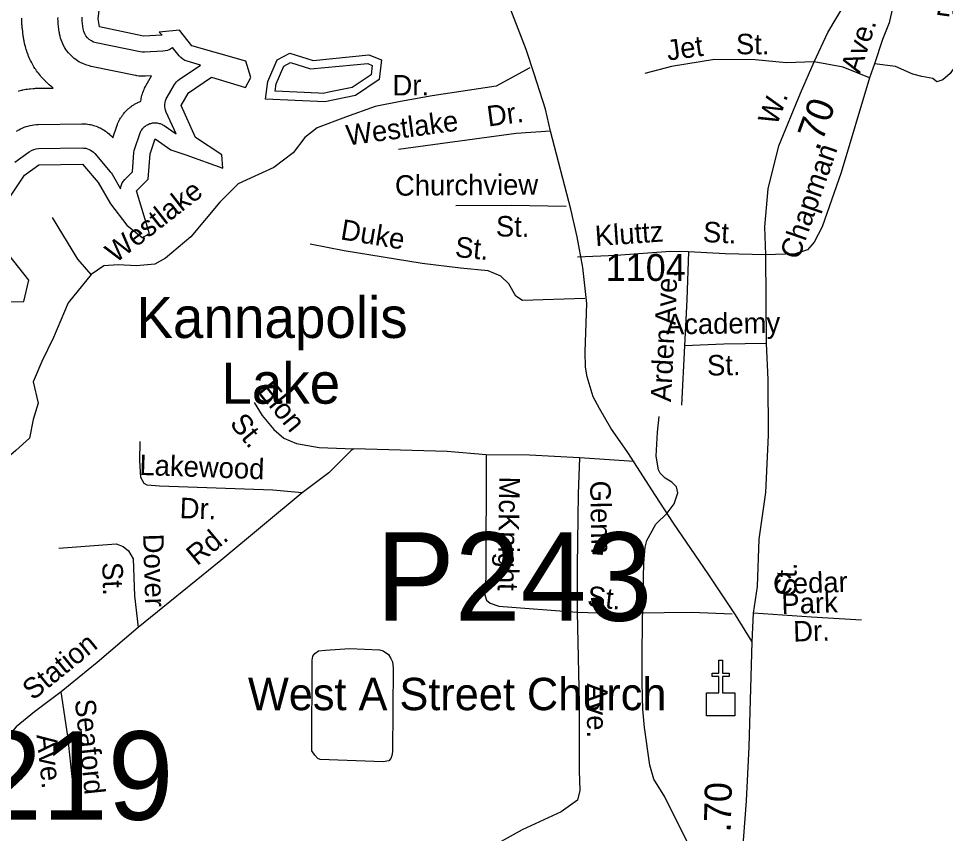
# Model space of a CAD drawing. Extents: x 1473865 to 1648260, y 639067 to 773536.
# Drawn here: x 1510919 to 1515215, y 645258 to 649038 of the extents above; entities that cross this region are included whole.
import ezdxf

# ---------------------------------------------------------------- set-up
doc = ezdxf.new("R2010")
doc.units = 0
for name, color, linetype in [('Exist Cultural Church CELL', 7, 'Continuous'), ('Exist Cultural Church Label', 7, 'Continuous'), ('Exist Hydrographic Buffer Line', 7, 'Continuous'), ('Exist Hydrographic Creek Single Shore', 7, 'Continuous'), ('Exist Hydrographic Lake Shore', 7, 'Continuous'), ('Exist Hydrographic Lake Shore Label', 7, 'Continuous'), ('Exist Hydrographic Misc Water Feature', 7, 'Continuous'), ('Exist Road Non-System Type 51', 7, 'Continuous'), ('Exist Road Non-System Type 51 Label', 7, 'Continuous'), ('Exist Road Secondary Mileage Hundredths English Label', 7, 'Continuous'), ('Exist Road Secondary Structure Pipe Number Label', 7, 'Continuous'), ('Exist Road Secondary Structure Standard Bridge Number Label', 7, 'Continuous'), ('Exist Road Secondary Type 51 Attributed', 7, 'Continuous'), ('Exist Road Secondary Type 51 Label', 7, 'Continuous'), ('Exist Road Secondary Type 51 Number Label', 7, 'Continuous')]:
    doc.layers.add(name, color=color, linetype=linetype)

msp = doc.modelspace()

# ---------------------------------------------------------------- linework, layer by layer
at = {"layer": 'Exist Cultural Church CELL'}
msp.add_lwpolyline([(1514108, 645909.7), (1514164.9, 645909.8), (1514164.9, 645986), (1514132.9, 645986), (1514132.9, 646001.9), (1514164.9, 646001.9), (1514164.9, 646062.1), (1514180.9, 646062.1), (1514180.9, 646001.9), (1514212.9, 646001.9), (1514212.9, 645986), (1514180.9, 645986), (1514180.9, 645909.8), (1514238.6, 645909.7), (1514238.6, 645803.3), (1514108, 645803.3)], close=True, dxfattribs=at)
at = {"layer": 'Exist Hydrographic Buffer Line'}
for points in [[(1510902.1, 648371.9), (1510968.4, 648420.2), (1510978.2, 648426.2), (1510988.8, 648430.7), (1511000, 648433.4), (1511011.4, 648434.5), (1511213.5, 648437.5), (1511221.8, 648437.2), (1511229.9, 648436), (1511237.8, 648433.9), (1511245.5, 648430.9), (1511252.8, 648427.1), (1511259.6, 648422.5), (1511265.9, 648417.3), (1511271.6, 648411.3), (1511344, 648326.9), (1511348.3, 648321.4), (1511352, 648315.5), (1511390.5, 648248.7), (1511392, 648256.9), (1511395.1, 648266.5), (1511399.5, 648275.7), (1511405.1, 648284.1), (1511411.8, 648291.8), (1511446.7, 648326.6), (1511453.6, 648416.5), (1511454.9, 648425.8), (1511457.3, 648434.8), (1511480.4, 648503.1), (1511481.9, 648507.2), (1511483.6, 648511.1), (1511485.6, 648515), (1511487.7, 648518.7), (1511490.1, 648522.3), (1511492.7, 648525.8), (1511495.5, 648529.1), (1511498.5, 648532.2), (1511501.6, 648535.2), (1511504.9, 648538), (1511508.4, 648540.5), (1511512, 648542.9), (1511515.8, 648545.1), (1511519.6, 648547), (1511523.6, 648548.8), (1511527.6, 648550.2), (1511531.8, 648551.5), (1511536, 648552.5), (1511540.2, 648553.3), (1511544.5, 648553.8), (1511548.8, 648554.1), (1511553.2, 648554.1), (1511557.5, 648553.9), (1511561.8, 648553.4), (1511566, 648552.7), (1511570.3, 648551.7), (1511574.4, 648550.5), (1511578.5, 648549.1), (1511582.5, 648547.4), (1511586.4, 648545.5), (1511590.1, 648543.4), (1511593.8, 648541), (1511648.9, 648503.3), (1511603.4, 648604.1), (1511600.2, 648612.5), (1511598, 648621.1), (1511596.9, 648630), (1511596.8, 648638.9), (1511597.8, 648647.7), (1511599.9, 648656.4), (1511602.9, 648664.8), (1511606.9, 648672.8), (1511641, 648731.2), (1511645.6, 648738.1), (1511650.9, 648744.5), (1511656.9, 648750.3), (1511663.6, 648755.4), (1511761.5, 648822.1), (1511700.9, 648839.4), (1511689.9, 648843.4), (1511679.7, 648849.1), (1511670.6, 648856.4), (1511662.6, 648864.9), (1511632.2, 648903.3), (1511628.4, 648900.1), (1511619.2, 648894.4), (1511609.3, 648890.1), (1511598.8, 648887.3), (1511588.1, 648886), (1511501.8, 648881.8), (1511492.4, 648882), (1511483.1, 648883.3), (1511278, 648925.5), (1511266.8, 648928.7), (1511256.2, 648933.7), (1511246.5, 648940.2), (1511238, 648948.1), (1511230.8, 648957.2), (1511225.1, 648967.4), (1511221, 648978.3), (1511218.7, 648989.7), (1511214, 649027), (1511213.4, 649035.9), (1511213.9, 649044.8)], [(1510909.7, 648515.5), (1510919.5, 648521.6), (1510927, 648525.8), (1510934.8, 648529.4), (1510945.4, 648533.9), (1510953.4, 648536.9), (1510961.7, 648539.3), (1510972.8, 648542.1), (1510981.2, 648543.9), (1510989.7, 648545), (1511001.2, 648546), (1511005.5, 648546.3), (1511009.8, 648546.5), (1511211.9, 648549.5), (1511214.9, 648549.5), (1511218, 648549.4), (1511226.2, 648549.1), (1511232.3, 648548.7), (1511238.4, 648547.9), (1511246.6, 648546.7), (1511252.6, 648545.6), (1511258.6, 648544.2), (1511266.5, 648542.1), (1511272.4, 648540.4), (1511278.2, 648538.3), (1511285.9, 648535.4), (1511291.5, 648533), (1511297.1, 648530.3), (1511304.3, 648526.5), (1511309.7, 648523.6), (1511314.9, 648520.3), (1511321.8, 648515.7), (1511326.8, 648512.2), (1511331.6, 648508.4), (1511337.9, 648503.1), (1511342.5, 648499), (1511346.8, 648494.7), (1511352.5, 648488.8), (1511354.6, 648486.5), (1511356, 648484.9), (1511374.3, 648538.9), (1511374.8, 648540.5), (1511375.3, 648542), (1511376.8, 648546), (1511378, 648549), (1511379.2, 648552), (1511381, 648556), (1511382.3, 648558.9), (1511383.7, 648561.8), (1511385.7, 648565.7), (1511387.2, 648568.5), (1511388.8, 648571.3), (1511390.9, 648575.1), (1511392.6, 648577.8), (1511394.4, 648580.6), (1511396.7, 648584.2), (1511398.6, 648586.8), (1511400.5, 648589.4), (1511403.1, 648592.9), (1511405, 648595.5), (1511407.1, 648598), (1511409.9, 648601.3), (1511412, 648603.7), (1511414.2, 648606.1), (1511417.1, 648609.2), (1511419.4, 648611.5), (1511421.7, 648613.8), (1511424.9, 648616.7), (1511427.2, 648618.9), (1511429.7, 648621), (1511433, 648623.8), (1511435.5, 648625.8), (1511438.1, 648627.8), (1511441.5, 648630.4), (1511444.1, 648632.3), (1511446.8, 648634.1), (1511450.4, 648636.5), (1511453.2, 648638.2), (1511455.9, 648639.9), (1511459.7, 648642), (1511462.5, 648643.6), (1511465.3, 648645.1), (1511469.2, 648647), (1511472.1, 648648.5), (1511475.1, 648649.8), (1511479, 648651.5), (1511482, 648652.7), (1511485, 648653.9), (1511485.9, 648654.2), (1511486.5, 648660.2), (1511487.5, 648666.8), (1511488.8, 648673.3), (1511490.8, 648682), (1511492.5, 648688.4), (1511494.6, 648694.8), (1511497.7, 648703.1), (1511500.2, 648709.3), (1511503, 648715.4), (1511507, 648723.3), (1511508.6, 648726.3), (1511510.2, 648729.2), (1511534.7, 648771.3), (1511507.2, 648770), (1511503.7, 648769.8), (1511500.1, 648769.8), (1511490.7, 648770), (1511483.7, 648770.3), (1511476.7, 648771.1), (1511467.4, 648772.4), (1511463.9, 648772.9), (1511460.5, 648773.6), (1511255.4, 648815.8), (1511251.1, 648816.8), (1511246.9, 648817.9), (1511235.7, 648821.1), (1511227.5, 648823.9), (1511219.4, 648827.2), (1511208.9, 648832.2), (1511201.1, 648836.1), (1511193.7, 648840.7), (1511184.1, 648847.2), (1511177, 648852.3), (1511170.4, 648858), (1511161.9, 648865.9), (1511155.7, 648872.1), (1511150.1, 648878.7), (1511142.9, 648887.8), (1511137.7, 648894.9), (1511133.2, 648902.3), (1511127.5, 648912.4), (1511123.5, 648920.2), (1511120.1, 648928.2), (1511116.1, 648939.1), (1511113.3, 648947.4), (1511111.3, 648955.8), (1511108.9, 648967.3), (1511108.1, 648971.5), (1511107.5, 648975.8), (1511102.9, 649013.1), (1511102.5, 649016.4), (1511102.2, 649019.8), (1511101.7, 649028.6), (1511101.4, 649035.3), (1511101.6, 649041.9)], [(1510917.8, 648701.5), (1510920.9, 648702.3), (1510932, 648705.1), (1510935.2, 648705.8), (1510938.3, 648706.5), (1510946.7, 648708.3), (1510953.1, 648709.5), (1510959.4, 648710.4), (1510968, 648711.6), (1510971.2, 648711.9), (1510974.4, 648712.3), (1510985.8, 648713.3), (1510987.4, 648713.5), (1510989, 648713.6), (1510993.3, 648713.9), (1510996.5, 648714.1), (1510999.7, 648714.2), (1511004, 648714.4), (1511005.7, 648714.4), (1511007.3, 648714.5), (1511079.5, 648715.5), (1511078, 648716.6), (1511072.8, 648720.6), (1511067.7, 648724.7), (1511061.1, 648730.4), (1511058.7, 648732.6), (1511056.3, 648734.8), (1511047.7, 648742.7), (1511045.3, 648744.9), (1511043, 648747.2), (1511036.9, 648753.4), (1511032.3, 648758.1), (1511028, 648762.9), (1511022.3, 648769.6), (1511020.3, 648772.1), (1511018.2, 648774.6), (1511011, 648783.8), (1511009, 648786.3), (1511007, 648789), (1511001.9, 648796), (1510998.2, 648801.3), (1510994.7, 648806.8), (1510990.1, 648814.3), (1510988.4, 648817.1), (1510986.8, 648819.9), (1510981.1, 648830), (1510979.5, 648832.9), (1510978, 648835.8), (1510974, 648843.5), (1510971.1, 648849.4), (1510968.5, 648855.4), (1510965.1, 648863.4), (1510963.9, 648866.4), (1510962.7, 648869.5), (1510958.7, 648880.4), (1510957.6, 648883.5), (1510956.5, 648886.5), (1510953.8, 648894.8), (1510951.9, 648901.1), (1510950.2, 648907.4), (1510948.1, 648915.8), (1510947.4, 648919), (1510946.7, 648922.2), (1510944.3, 648933.6), (1510944, 648935.2), (1510943.7, 648936.8), (1510942.9, 648941.1), (1510942.4, 648944.3), (1510941.9, 648947.5), (1510941.2, 648951.8), (1510941, 648953.4), (1510940.8, 648955.1), (1510936.2, 648992.4), (1510936, 648993.6), (1510935.9, 648994.8), (1510935.5, 648998.1), (1510935.3, 649000.6), (1510935, 649003.1), (1510934.8, 649006.4), (1510934.7, 649007.7), (1510934.6, 649008.9), (1510934, 649017.8), (1510933.9, 649020.3), (1510933.8, 649022.8), (1510933.5, 649029.4), (1510933.4, 649034.4), (1510933.5, 649039.4)], [(1512356.6, 648695.7), (1512330.5, 648690.2), (1512308.8, 648691.2), (1512108.8, 648701.2), (1512112.8, 648734.5), (1512148.9, 648817.4), (1512179.8, 648834.2), (1512271.4, 648804.5), (1512536.8, 648829.3), (1512557.8, 648820.6), (1512553.1, 648777.3), (1512465, 648718.6), (1512356.6, 648695.7)]]:
    msp.add_lwpolyline(points, dxfattribs=at)
at = {"layer": 'Exist Hydrographic Creek Single Shore'}
msp.add_lwpolyline([(1514059.6, 645135.8), (1513913.6, 645428.4), (1513863, 645509.3), (1513844.3, 645575.6), (1513819.4, 645750), (1513812.9, 645834), (1513809.9, 645888.1), (1513809.3, 645966), (1513809.4, 646085.9), (1513810.7, 646238.9), (1513817.2, 646513.5), (1513822.4, 646585.4), (1513831, 646617.2), (1513872.4, 646692.3), (1513925.3, 646743.3), (1513958.1, 646786.7), (1513975, 646838.3), (1513967.5, 646866.5), (1513945.9, 646886.8), (1513916.2, 646905.4), (1513892.7, 646929.8), (1513885, 646944), (1513874.1, 647008.1), (1513880.2, 647119.9), (1513887.4, 647191.7)], dxfattribs=at)
at = {"layer": 'Exist Hydrographic Lake Shore'}
for points in [[(1511995.8, 648764.3), (1511971.8, 648840.4), (1511721.4, 648911.5), (1511664.1, 648983.9), (1511570.6, 648974.8), (1511584.5, 648960.9), (1511498.2, 648956.7), (1511293.1, 648999), (1511288.4, 649036.3), (1511305.1, 649183)], [(1512073.7, 648745.1), (1512117.7, 648845.9), (1512175.8, 648877.6), (1512283.7, 648842.6), (1512542.8, 648870.2), (1512600.7, 648846), (1512590.8, 648754.3), (1512480.8, 648681), (1512338.8, 648651), (1512063.8, 648663.2), (1512073.7, 648745.1)], [(1510810.3, 648110.4), (1510946.2, 648311.2), (1511012.6, 648359.5), (1511214.7, 648362.5), (1511287.1, 648278.1), (1511344.4, 648178.5), (1511419.8, 648079), (1511492.2, 648021.7), (1511525.3, 648039.8), (1511464.7, 648238.7), (1511519.3, 648293.1), (1511528.4, 648410.8), (1511551.4, 648479.1), (1511624.9, 648428.9), (1511694.7, 648405.6), (1511866.2, 648344.4), (1511860.1, 648405.6), (1511738.8, 648486.5), (1511671.7, 648635), (1511705.8, 648693.4), (1511812.3, 648766), (1511970.3, 648718.2), (1511995.8, 648764.3)], [(1510873.8, 647723.1), (1510943.2, 647726.1), (1510966.2, 647823.8), (1510873.5, 647941.9)]]:
    msp.add_lwpolyline(points, dxfattribs=at)
at = {"layer": 'Exist Hydrographic Misc Water Feature'}
msp.add_lwpolyline([(1512453.1, 646115.7), (1512592.1, 646110.4), (1512608.2, 646105.4), (1512633.4, 646088.7), (1512644.6, 646069.9), (1512651.3, 646053.5), (1512655.3, 646025.6), (1512652, 645636.3), (1512649.3, 645620.1), (1512644.4, 645606.3), (1512634.9, 645594.9), (1512609.3, 645590.8), (1512317.3, 645601.7), (1512305.9, 645606.5), (1512292.2, 645620.7), (1512278.7, 645641.9), (1512280.3, 646061.4), (1512283, 646079.9), (1512292.6, 646093.6), (1512309, 646104.9), (1512341.6, 646108.8), (1512453.1, 646115.7)], dxfattribs=at)
at = {"layer": 'Exist Road Non-System Type 51'}
for p, q in [((1514885.5, 648828), (1514862.5, 648762.4)), ((1514005.3, 647520), (1513991.1, 647244.4)), ((1513772, 646983.8), (1513519.3, 646999.8))]:
    msp.add_line(p, q, dxfattribs=at)
for points in [[(1514769.5, 649133.8), (1514813.5, 649120.6), (1514889, 649116), (1514930.4, 649101), (1514971.2, 649093.2), (1514954.3, 649017.1), (1514923.5, 648940.1), (1514885.5, 648828)], [(1515493.9, 648984.4), (1515449.6, 648967.1), (1515369.7, 648978.3), (1515329.8, 648981.1), (1515315.2, 648974.8), (1515305.5, 648959.4), (1515288.5, 648889.7), (1515257.3, 648812.1), (1515236.7, 648782.5), (1515202.3, 648752.9), (1515175.3, 648744.1), (1515156.6, 648759.6), (1515105.5, 648768.4), (1515063.3, 648779.1), (1514982.9, 648814.6), (1514885.5, 648828)], [(1514606.7, 648836.6), (1514477, 648832.2), (1514332.9, 648847), (1514144.8, 648848), (1513944.7, 648814.6), (1513820.8, 648782.8)], [(1514862.5, 648762.4), (1514740.9, 648812.4), (1514606.7, 648836.6)], [(1513288.7, 648809.2), (1513132, 648724), (1512836.4, 648679.2), (1512688.6, 648652.3), (1512572.2, 648629.9), (1512433.3, 648580.5), (1512303.4, 648531.2), (1512245.2, 648486.4), (1512191.5, 648414.7), (1512101.9, 648347.4), (1511994.4, 648298.1), (1511936.2, 648271.2), (1511851.1, 648186.1), (1511716.7, 648024.7), (1511600.3, 647926.1), (1511551, 647899.2), (1511465.9, 647890.2), (1511380.8, 647894.7), (1511313.6, 647890.2), (1511255.4, 647849.9)], [(1514862.5, 648762.4), (1514731.6, 648324.4), (1514643.7, 648071.8), (1514606.6, 648000.6), (1514576.1, 647965), (1514517.9, 647945.9), (1514381.8, 647942.1)], [(1513384.3, 648515.5), (1513224.5, 648504.3), (1512679.4, 648430.8)], [(1513457.2, 648166.6), (1513201.4, 648170.6), (1512945.4, 648168.7)], [(1511255.4, 647849.9), (1511192.7, 647921.6), (1511076.3, 648114.3)], [(1513543.1, 647739.5), (1513254.5, 647729.9), (1513222.9, 647750.3), (1513191.8, 647806.8), (1513154.4, 647843.3), (1513094.6, 647868.4), (1512966.8, 647880.3), (1512789.2, 647901.1), (1512428.2, 647960.8), (1512270.7, 647991.2)], [(1514024.1, 647955.7), (1513940, 647957), (1513687.8, 647939), (1513509.5, 647930.4)], [(1514024.1, 647955.7), (1514016.6, 647733.9), (1514005.3, 647520)], [(1514381.8, 647942.1), (1514194, 647947), (1514024.1, 647955.7)], [(1511255.4, 647849.9), (1511147.9, 647719.9), (1511080.7, 647558.5), (1511027, 647446.4), (1510986.7, 647352.3), (1511009.1, 647253.7), (1510986.7, 647177.5), (1510968.8, 647092.3), (1510906.1, 647034), (1510821, 646962.3), (1510767.2, 646868.2)], [(1514385.4, 647530), (1514187.3, 647527.2), (1514005.3, 647520)], [(1512011.4, 647257.5), (1512048.4, 647196.9), (1512101.3, 647132), (1512148.7, 647091.4), (1512206.4, 647066.4), (1512312.1, 647048.7), (1512471.9, 647042.3)], [(1512232.8, 646838), (1512097, 646850.1), (1511571.3, 646868.5), (1511515.4, 646873.3), (1511501.6, 646881.6), (1511485.9, 646909.9), (1511481.1, 646987.8), (1511482.5, 647075.8)], [(1512471.9, 647042.3), (1512462, 647036.5), (1512356.2, 646930.2), (1512232.8, 646838)], [(1513085.4, 647014.5), (1512905.8, 647029.3), (1512471.9, 647042.3)], [(1513085.4, 647014.5), (1513084.8, 646446.6), (1513079.5, 646364.7), (1513087, 646340.7), (1513104.7, 646326.4), (1513144.7, 646311.8), (1513508.1, 646284)], [(1513519.3, 646999.8), (1513287.5, 647013.4), (1513085.4, 647014.5)], [(1513519.3, 646999.8), (1513512.6, 646833.8), (1513507.4, 646497.9), (1513508.1, 646284)], [(1512232.8, 646838), (1511855.9, 646524), (1511473.3, 646214.2)], [(1511104.9, 646581.8), (1511371.2, 646601.6), (1511403, 646589.2), (1511428.6, 646568.7), (1511450.1, 646532.4), (1511455.4, 646360.4), (1511473.3, 646214.2)], [(1513508.1, 646284), (1513517.6, 645862), (1513516.8, 645548.1), (1513519.4, 645458), (1513508.7, 645412.2), (1513433.8, 645359.2), (1513252.6, 645274.3), (1513141.5, 645213.9), (1513096.9, 645166.7), (1513044.4, 645001.5), (1513041.3, 644987.7)], [(1513508.1, 646284), (1513656.1, 646279.6), (1514037.7, 646285.1), (1514226.5, 646276.6)], [(1514825.6, 646247.2), (1514594.7, 646261.4), (1514325.5, 646280)], [(1511473.3, 646214.2), (1511282.7, 646051.1), (1511116.5, 645915.8)], [(1511116.5, 645915.8), (1510993.1, 645821.7), (1510908.1, 645753.1), (1510830.6, 645662.3), (1510742.7, 645539.8), (1510635.8, 645347.4), (1510567.4, 645213.6)], [(1511170, 645492.9), (1511147.3, 645709.3), (1511116.5, 645915.8)]]:
    msp.add_lwpolyline(points, dxfattribs=at)
at = {"layer": 'Exist Road Secondary Type 51 Attributed'}
for points in [[(1514319.3, 646146.9), (1514325.5, 646280), (1514344, 646403.8), (1514351.2, 646623.7), (1514382.7, 646840.3), (1514394.9, 647106), (1514392.9, 647363.9), (1514385.4, 647530), (1514381.8, 647942.1), (1514377.8, 648072), (1514392.5, 648247.8), (1514442.8, 648447.5), (1514543.3, 648691.4), (1514606.7, 648836.6), (1514669.9, 648973.1), (1514756, 649117.8), (1515029.6, 649613.7), (1515084.1, 649706.5), (1515129.6, 649811.8), (1515173.9, 650013.3), (1515212.7, 650181.6), (1515240.6, 650324.2)], [(1514319.3, 646146.9), (1514242, 646272.7), (1514115.1, 646461.6), (1513954.2, 646697), (1513871.1, 646825.9), (1513743.1, 647025.5), (1513663.2, 647138.4), (1513611.6, 647229), (1513582.4, 647282.6), (1513554.6, 647376.5), (1513546.8, 647421.3), (1513544.9, 647491.5), (1513553.2, 647715.9), (1513533.7, 647882.5), (1513507.9, 648026.1), (1513478.6, 648154), (1513384.3, 648515.5), (1513360.8, 648617.3), (1513308.7, 648781.4), (1513271.7, 648894.4), (1513197.9, 649085.4)], [(1514349.8, 642909.8), (1514352.2, 643113.1), (1514342.4, 643368.7), (1514327.7, 643720.3), (1514291.5, 644135.5), (1514271.5, 644293.6), (1514255.5, 644503.9), (1514271.8, 644657.8), (1514287.1, 644929.8), (1514272.5, 645144.2), (1514292.6, 645409.8), (1514304.5, 645659.7), (1514319.3, 646146.9)]]:
    msp.add_lwpolyline(points, dxfattribs=at)

# ---------------------------------------------------------------- texts
at = {"layer": 'Exist Cultural Church Label'}
msp.add_text('West A Street Church', height=150, dxfattribs=at).set_placement((1511981.9, 645830))
at = {"layer": 'Exist Hydrographic Lake Shore Label'}
for s, p in [('Kannapolis', (1511464.8, 647556.3)), ('Lake', (1511858.6, 647251.4))]:
    msp.add_text(s, height=190, dxfattribs=at).set_placement(p)
at = {"layer": 'Exist Road Non-System Type 51 Label'}
for s, rotation, p in [('Leazer', 352.0022, (1515166.4, 649056.5)), ('Ave.', 72.0851, (1514818, 648779.1)), ('Jet', 7.9603, (1513928.6, 648842.1)), ('St.', 359.6982, (1514243.6, 648872.3)), ('Dr.', 7.6736, (1513096, 648536.6)), ('Westlake', 7.6736, (1512443.5, 648448.7)), ('Chapman', 70.8019, (1514535, 647915.1)), ('Churchview', 0.412, (1512663.7, 648215.9)), ('Westlake', 37.8995, (1511368.1, 647900.6)), ('Duke', 350.6083, (1512407.2, 648014.2)), ('St.', 359.114, (1513130.6, 648027.4)), ('St.', 357.0928, (1514089.3, 648001.6)), ('Kluttz', 4.0644, (1513593.5, 647981.7)), ('St.', 354.6449, (1512938.8, 647932.4)), ('Ave.', 88.0689, (1513963.4, 647615.8)), ('Academy', 0.812, (1513919.7, 647572.6)), ('Arden', 87.0573, (1513942.5, 647258.2)), ('St.', 0.812, (1514110.3, 647381.8)), ('Elon', 309.1931, (1512020.9, 647308.5)), ('St.', 309.1931, (1511893.7, 647158.4)), ('Lakewood', 357.9951, (1511477.7, 646921.1)), ('McKnight', 269.0907, (1513147.5, 646914.2)), ('Glenn', 271.1627, (1513567.4, 646893.7)), ('Dr.', 357.9951, (1511664.3, 646721)), ('Dover', 271.7765, (1511495.8, 646646.6)), ('Rd.', 39.7937, (1511746.1, 646496.6)), ('St.', 271.7765, (1511306.3, 646515.3)), ('Cedar', 1.7536, (1514417.1, 646368.2)), ('St.', 353.7341, (1513551.3, 646312.7)), ('Park', 1.7536, (1514455.9, 646275.4)), ('Dr.', 1.7536, (1514510.5, 646147.8)), ('Station', 39.1503, (1510985.2, 645872.4)), ('Ave.', 269.8665, (1513554, 645954.6)), ('Seaford', 275.9755, (1511179.2, 645877.2)), ('Ave.', 275.9755, (1511001.7, 645714.9))]:
    msp.add_text(s, height=95, rotation=rotation, dxfattribs=at).set_placement(p)
msp.add_text('Dr.', height=95, dxfattribs=at).set_placement((1512651.9, 648681))
at = {"layer": 'Exist Road Secondary Mileage Hundredths English Label'}
for rotation, p in [(70.179, (1514627.8, 648419.5)), (88.5736, (1514219.4, 645262.5))]:
    msp.add_text('.70', height=125, rotation=rotation, dxfattribs=at).set_placement(p)
at = {"layer": 'Exist Road Secondary Structure Pipe Number Label'}
msp.add_text('P243', height=410.1, dxfattribs=at).set_placement((1512574.6, 646244.5))
at = {"layer": 'Exist Road Secondary Structure Standard Bridge Number Label'}
msp.add_text('219', height=410.1, dxfattribs=at).set_placement((1510721.9, 645321.7))
at = {"layer": 'Exist Road Secondary Type 51 Label'}
for s, rotation, p in [('W.', 69.3472, (1514432.6, 648537.2)), ('St.', 88.1146, (1514521.5, 646358.6))]:
    msp.add_text(s, height=95, rotation=rotation, dxfattribs=at).set_placement(p)
at = {"layer": 'Exist Road Secondary Type 51 Number Label'}
msp.add_text('1104', height=125, dxfattribs=at).set_placement((1513639.5, 647820.8))

doc.saveas('drawing.dxf')
